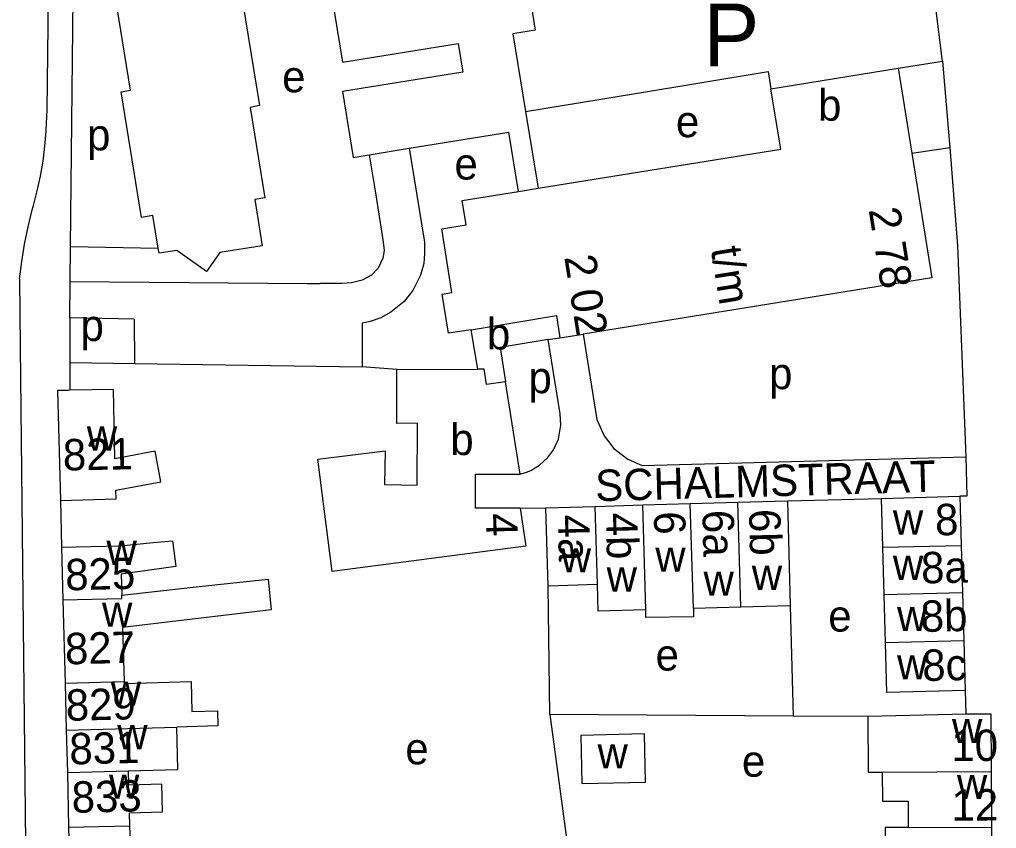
# Model space of a CAD drawing. Extents: x 161141 to 163125, y 381621 to 383200.
# Drawn here: x 162094.9 to 162219.4, y 382227.5 to 382330.5 of the extents above; entities that cross this region are included whole.
import ezdxf

# ---------------------------------------------------------------- set-up
doc = ezdxf.new("R2010")
doc.units = 0
for name, color, linetype in [('BLT_Basislijn', 7, 'Continuous'), ('BLT_Bebouwing', 7, 'Continuous'), ('BLT_Centroide', 7, 'Continuous'), ('BLT_Huisnummer', 7, 'Continuous'), ('BLT_Huisnummer_ tussenligend', 7, 'Continuous'), ('BLT_Huisnummer_reeks', 7, 'Continuous'), ('BLT_Onderdoorgang_en_onderverdeling', 7, 'Continuous'), ('BLT_Onderverdeling_panden', 7, 'Continuous'), ('BLT_Straatnaam_verkleind', 7, 'Continuous'), ('BLT_Tekst_parkeren', 7, 'Continuous')]:
    doc.layers.add(name, color=color, linetype=linetype)

msp = doc.modelspace()

# ---------------------------------------------------------------- linework, layer by layer
at = {"layer": 'BLT_Basislijn'}
for p, q in [((162098.45, 382318.95), (162098.74, 382343.94)), ((162101.44, 382301.57), (162101.87, 382343.56)), ((162206.92, 382324.28), (162212.55, 382325.18)), ((162208.65, 382313.49), (162213.47, 382314.17)), ((162101.4, 382297.12), (162101.44, 382301.57)), ((162101.44, 382301.57), (162112.6, 382301.36)), ((162094.94, 382297.48), (162095.03, 382288.78)), ((162101.35, 382292.49), (162101.4, 382297.12)), ((162101.4, 382297.12), (162131.57, 382296.89)), ((162131.57, 382296.89), (162133.24, 382296.87)), ((162136, 382296.87), (162133.24, 382296.87)), ((162101.35, 382292.49), (162101.35, 382286.83)), ((162109.56, 382292.33), (162101.35, 382292.49)), ((162109.56, 382292.33), (162109.59, 382286.7)), ((162138.59, 382291.8), (162138.59, 382286.24)), ((162101.35, 382286.83), (162101.35, 382283.27)), ((162101.35, 382286.83), (162109.59, 382286.7)), ((162109.59, 382286.7), (162138.59, 382286.24)), ((162143.02, 382285.92), (162138.59, 382286.24)), ((162100.14, 382269.24), (162100.29, 382263.29)), ((162192.78, 382269.19), (162204.76, 382269.5)), ((162158.72, 382268.28), (162162, 382268.32)), ((162162.5, 382241.97), (162162.29, 382258.34)), ((162193.14, 382255.83), (162193.52, 382241.78)), ((162215.44, 382245.06), (162215.52, 382242.01)), ((162162.5, 382241.97), (162165.72, 382218.15)), ((162193.52, 382241.78), (162162.5, 382241.97)), ((162203.03, 382241.72), (162193.52, 382241.78))]:
    msp.add_line(p, q, dxfattribs=at)
for points in [[(162212.55, 382325.18), (162211.56, 382332.96), (162207.61, 382350.14), (162206.56, 382354.82)], [(162212.55, 382325.18), (162213.27, 382316.66), (162213.47, 382314.17)], [(162159.42, 382318.78), (162173.41, 382321.08), (162190.33, 382323.86), (162190.68, 382321.68)], [(162096.72, 382306.82), (162097.2, 382308.68), (162097.6, 382310.56), (162097.93, 382312.45), (162098.18, 382314.36), (162098.35, 382316.27), (162098.43, 382318.19), (162098.45, 382318.95)], [(162144.6, 382314.09), (162146.55, 382302.15), (162146.55, 382300.68), (162146.44, 382299.4), (162146.02, 382297.93), (162145.05, 382295.98), (162143.93, 382294.6), (162142.26, 382293.21), (162140.96, 382292.48), (162139.6, 382292.02), (162138.59, 382291.8)], [(162213.47, 382314.17), (162214.46, 382301.65), (162215.51, 382274.78)], [(162139.51, 382313.26), (162140.24, 382308.67), (162141.07, 382303.52), (162141.28, 382302.14), (162141.39, 382301.07), (162141.23, 382300.1), (162140.64, 382298.83), (162139.78, 382297.94), (162138.59, 382297.31), (162137.22, 382296.95), (162136, 382296.87)], [(162094.94, 382297.48), (162095.23, 382299.69), (162095.59, 382301.89), (162096.04, 382304.07), (162096.56, 382306.24), (162096.72, 382306.82)], [(162166.74, 382290.43), (162168.5, 382279.57), (162169.44, 382277.48), (162170.68, 382275.88), (162172.46, 382274.49), (162174.27, 382273.7), (162215.51, 382274.78)], [(162095.03, 382288.78), (162095.93, 382205.88), (162101.83, 382201.31)], [(162158.75, 382272.61), (162159.56, 382272.84), (162160.07, 382273.06), (162161.2, 382273.74), (162162.26, 382274.7), (162162.96, 382275.68), (162163.6, 382277.06), (162163.92, 382278.83), (162163.84, 382280.27), (162162.32, 382289.72)], [(162215.51, 382274.78), (162215.65, 382269.79), (162214.75, 382269.77)]]:
    msp.add_lwpolyline(points, dxfattribs=at)
at = {"layer": 'BLT_Bebouwing'}
for p, q in [((162153.32, 382285.98), (162152.49, 382290.99)), ((162162.32, 382289.72), (162163.8, 382289.96)), ((162163.8, 382289.96), (162166.74, 382290.43)), ((162101.35, 382283.27), (162101.15, 382283.26)), ((162100.14, 382269.24), (162107.25, 382269.43)), ((162168.28, 382268.49), (162174.36, 382268.67)), ((162174.36, 382268.67), (162180.41, 382268.84)), ((162180.41, 382268.84), (162186.48, 382269.01)), ((162186.48, 382269.01), (162192.78, 382269.19)), ((162192.78, 382269.19), (162193.14, 382255.83)), ((162204.76, 382269.5), (162214.75, 382269.77)), ((162204.93, 382263.31), (162204.76, 382269.5)), ((162214.75, 382269.77), (162214.92, 382263.52)), ((162162, 382268.32), (162168.28, 382268.49)), ((162162.29, 382258.34), (162162, 382268.32)), ((162100.29, 382263.29), (162100.46, 382256.57)), ((162205.1, 382257.23), (162204.93, 382263.31)), ((162214.92, 382263.52), (162215.09, 382257.46)), ((162168.59, 382258.52), (162162.29, 382258.34)), ((162168.68, 382255.14), (162168.59, 382258.52)), ((162215.09, 382257.46), (162215.26, 382251.39)), ((162205.27, 382251.15), (162205.1, 382257.23)), ((162174.75, 382255.31), (162168.68, 382255.14)), ((162186.83, 382255.65), (162180.81, 382255.48)), ((162193.14, 382255.83), (162186.83, 382255.65)), ((162215.26, 382251.39), (162215.44, 382245.06)), ((162205.45, 382244.78), (162205.27, 382251.15)), ((162100.74, 382245.97), (162100.89, 382240)), ((162215.44, 382245.06), (162205.45, 382244.78)), ((162218.81, 382234.73), (162218.77, 382242.03)), ((162100.89, 382240), (162101.03, 382234.62)), ((162101.03, 382234.62), (162101.18, 382227.62)), ((162218.85, 382227.65), (162218.81, 382234.73)), ((162101.18, 382227.62), (162101.39, 382220.01)), ((162109.23, 382220.2), (162109.01, 382227.8)), ((162218.89, 382220.73), (162218.85, 382227.65))]:
    msp.add_line(p, q, dxfattribs=at)
for points in [[(162132.05, 382349.78), (162136.08, 382325.07), (162150.85, 382327.42), (162151.43, 382323.8), (162136.09, 382321.32), (162137.45, 382312.92), (162139.51, 382313.26)], [(162112.6, 382301.36), (162111.93, 382305.51), (162110.47, 382305.27), (162107.89, 382321.3), (162109.06, 382321.49), (162106.61, 382336.74), (162107.77, 382336.94), (162106.49, 382344.64)], [(162126.98, 382339.6), (162123.58, 382339.09), (162124.24, 382335.14), (162123, 382334.89), (162125.53, 382319.54), (162124.31, 382319.3), (162126.2, 382307.78), (162124.94, 382307.58), (162125.87, 382301.67)], [(162159.79, 382334.47), (162160.66, 382329.15), (162157.8, 382328.67), (162159.42, 382318.78)], [(162190.68, 382321.68), (162206.92, 382324.28)], [(162206.92, 382324.28), (162208.66, 382313.49)], [(162161.02, 382309), (162191.94, 382313.97), (162190.68, 382321.68)], [(162159.42, 382318.78), (162161.02, 382309)], [(162144.6, 382314.09), (162157.28, 382316.16)], [(162158.51, 382308.59), (162157.28, 382316.16)], [(162139.51, 382313.26), (162144.6, 382314.09)], [(162208.66, 382313.49), (162211.21, 382297.6)], [(162148.8, 382295.51), (162150.04, 382295.71), (162148.73, 382303.83), (162151.83, 382304.33), (162151.33, 382307.45), (162158.51, 382308.59)], [(162125.87, 382301.67), (162120.48, 382300.8), (162118.77, 382298.4), (162114.98, 382301.09), (162112.71, 382300.72), (162112.61, 382301.36)], [(162211.21, 382297.6), (162166.74, 382290.43)], [(162152.49, 382290.99), (162149.6, 382290.54), (162148.8, 382295.51)], [(162162.32, 382289.72), (162156.17, 382288.73), (162156.87, 382284.37)], [(162158.72, 382268.28), (162159.46, 382263.42), (162134.77, 382260.2), (162132.95, 382274.48), (162141.51, 382275.57), (162141.44, 382271.27), (162145.62, 382271.2), (162145.63, 382279.07), (162143.03, 382279.06), (162143.02, 382285.92)], [(162143.02, 382285.92), (162153.32, 382285.98)], [(162158.75, 382272.61), (162156.87, 382284.37)], [(162101.15, 382283.26), (162099.77, 382283.24), (162100.14, 382269.24)], [(162107.25, 382269.43), (162107.21, 382270.55), (162112.93, 382271.61), (162112.21, 382275.51), (162107.08, 382274.55), (162106.92, 382283.37), (162101.35, 382283.27)], [(162158.72, 382268.28), (162153.06, 382268.24), (162153.05, 382272.58), (162158.75, 382272.61)], [(162100.29, 382263.29), (162107.8, 382263.48), (162111.95, 382263.89)], [(162111.95, 382263.89), (162114.43, 382264.1), (162114.85, 382260.84), (162111.79, 382260.41)], [(162111.79, 382260.41), (162107.9, 382259.86), (162107.97, 382257.17)], [(162107.97, 382257.17), (162117.81, 382258.29), (162126.63, 382259.22), (162127.01, 382255.32), (162108.06, 382253.05), (162108.26, 382246.17)], [(162100.46, 382256.57), (162100.74, 382245.97)], [(162180.81, 382255.48), (162180.84, 382254.42), (162174.74, 382254.34), (162174.75, 382255.31)], [(162108.26, 382246.17), (162108.26, 382245.95), (162116.82, 382246.17), (162116.91, 382242.37), (162120.15, 382242.46), (162120.21, 382240.53), (162114.98, 382240.39)], [(162215.52, 382242.01), (162213.77, 382242), (162203.03, 382241.72)], [(162203.03, 382241.72), (162203.07, 382234.64), (162204.88, 382234.65)], [(162218.77, 382242.03), (162215.52, 382242.01)], [(162108.82, 382234.83), (162115.12, 382234.99), (162114.98, 382240.39)], [(162109.01, 382227.8), (162108.96, 382229.48), (162113.15, 382229.59), (162113.05, 382233.1), (162108.87, 382232.98), (162108.82, 382234.83)], [(162204.88, 382234.65), (162204.9, 382230.95), (162208.16, 382230.97), (162208.18, 382227.59)], [(162208.18, 382227.59), (162205.23, 382227.58), (162205.24, 382224.58), (162210.76, 382224.62), (162210.77, 382224.04), (162210.43, 382224.04), (162210.04, 382223.61), (162210.06, 382221.39), (162210.68, 382221.07), (162210.68, 382220.72)]]:
    msp.add_lwpolyline(points, dxfattribs=at)
msp.add_lwpolyline([(162166.47, 382239.33), (162166.6, 382233.21), (162174.71, 382233.38), (162174.58, 382239.51)], close=True, dxfattribs=at)
at = {"layer": 'BLT_Onderdoorgang_en_onderverdeling'}
msp.add_line((162158.51, 382308.59), (162161.02, 382309.01), dxfattribs=at)
for points in [[(162152.49, 382290.99), (162163.35, 382292.78), (162163.8, 382289.96)], [(162156.87, 382284.37), (162154.45, 382283.99), (162154.14, 382285.96), (162153.32, 382285.98)]]:
    msp.add_lwpolyline(points, dxfattribs=at)
at = {"layer": 'BLT_Onderverdeling_panden'}
for p, q in [((162174.75, 382255.31), (162174.36, 382268.67)), ((162180.81, 382255.48), (162180.41, 382268.84)), ((162186.83, 382255.65), (162186.48, 382269.01)), ((162168.59, 382258.52), (162168.28, 382268.49)), ((162204.93, 382263.31), (162214.92, 382263.52)), ((162215.09, 382257.46), (162205.1, 382257.23)), ((162205.27, 382251.15), (162215.26, 382251.39)), ((162100.74, 382245.97), (162108.26, 382246.17)), ((162100.89, 382240), (162114.98, 382240.39)), ((162101.03, 382234.62), (162108.82, 382234.83)), ((162204.88, 382234.65), (162218.81, 382234.73)), ((162101.18, 382227.62), (162109.01, 382227.8)), ((162208.18, 382227.59), (162218.85, 382227.65))]:
    msp.add_line(p, q, dxfattribs=at)
msp.add_lwpolyline([(162100.46, 382256.57), (162107.98, 382256.75), (162107.97, 382257.17)], dxfattribs=at)

# ---------------------------------------------------------------- texts
at = {"layer": 'BLT_Centroide'}
for s, p in [('e', (162128.4, 382321.22)), ('b', (162196.69, 382317.6)), ('e', (162178.58, 382315.5)), ('p', (162103.54, 382313.82)), ('e', (162150.36, 382310.11)), ('p', (162102.71, 382289.55)), ('b', (162154.5, 382288.47)), ('p', (162190.45, 382283.42)), ('p', (162159.79, 382282.9)), ('w', (162103.51, 382275.59)), ('b', (162149.83, 382275.03)), ('w', (162206.23, 382264.9)), ('w', (162106.02, 382261.03)), ('w', (162163.91, 382260.08)), ('w', (162175.95, 382260.18)), ('w', (162206.23, 382259.12)), ('w', (162169.75, 382257.64)), ('w', (162182.1, 382257.11)), ('w', (162188.25, 382257.85)), ('w', (162105.45, 382253.16)), ('e', (162197.99, 382252.54)), ('w', (162206.76, 382252.6)), ('e', (162175.99, 382247.58)), ('w', (162206.76, 382246.45)), ('w', (162106.56, 382243.09)), ('w', (162213.76, 382238.34)), ('w', (162107.39, 382237.56)), ('e', (162144.1, 382235.64)), ('w', (162168.59, 382235.13)), ('e', (162186.99, 382234.06)), ('w', (162106.34, 382231.25)), ('w', (162214.39, 382231.22))]:
    msp.add_text(s, height=4, dxfattribs=at).set_placement(p)
at = {"layer": 'BLT_Huisnummer'}
for s, rotation, p in [('821', 1.0617, (162100.49, 382273.05)), ('8', 1.3278, (162211.64, 382264.78)), ('4', 271.3278, (162154.37, 382267.58)), ('4b', 271.3278, (162169.65, 382267.65)), ('6', 271.3278, (162175.76, 382267.82)), ('6a', 271.3278, (162181.95, 382268)), ('6b', 271.3278, (162187.89, 382268.12)), ('4a', 271.3278, (162163.53, 382267.41)), ('8a', 1.3278, (162209.86, 382258.66)), ('825', 1.3782, (162100.8, 382257.78)), ('8c', 1.3278, (162210.01, 382246.24)), ('829', 1.3756, (162100.87, 382241.17)), ('10', 0.3395, (162213.69, 382236.04)), ('833', 1.3742, (162101.62, 382229.45))]:
    msp.add_text(s, height=4, rotation=rotation, dxfattribs=at).set_placement(p)
at = {"layer": 'BLT_Huisnummer_ tussenligend'}
for s, rotation, p in [('8b', 1.3278, (162209.82, 382252.49)), ('827', 1.3782, (162100.77, 382248.36)), ('831', 1.3756, (162101.33, 382235.61)), ('12', 0.3395, (162213.71, 382228.46))]:
    msp.add_text(s, height=4, rotation=rotation, dxfattribs=at).set_placement(p)
at = {"layer": 'BLT_Huisnummer_reeks'}
for s, p in [('2 78', (162203.13, 382306.28)), ('t/m', (162183.01, 382301.3)), ('2 02', (162164.34, 382300.25))]:
    msp.add_text(s, height=4, rotation=279.0852, dxfattribs=at).set_placement(p)
at = {"layer": 'BLT_Straatnaam_verkleind'}
msp.add_text('SCHALMSTRAAT', height=4, rotation=1.6184, dxfattribs=at).set_placement((162168.35, 382269.13))
at = {"layer": 'BLT_Tekst_parkeren'}
msp.add_text('P', height=8, dxfattribs=at).set_placement((162182.07, 382324.52))

doc.saveas('drawing.dxf')
